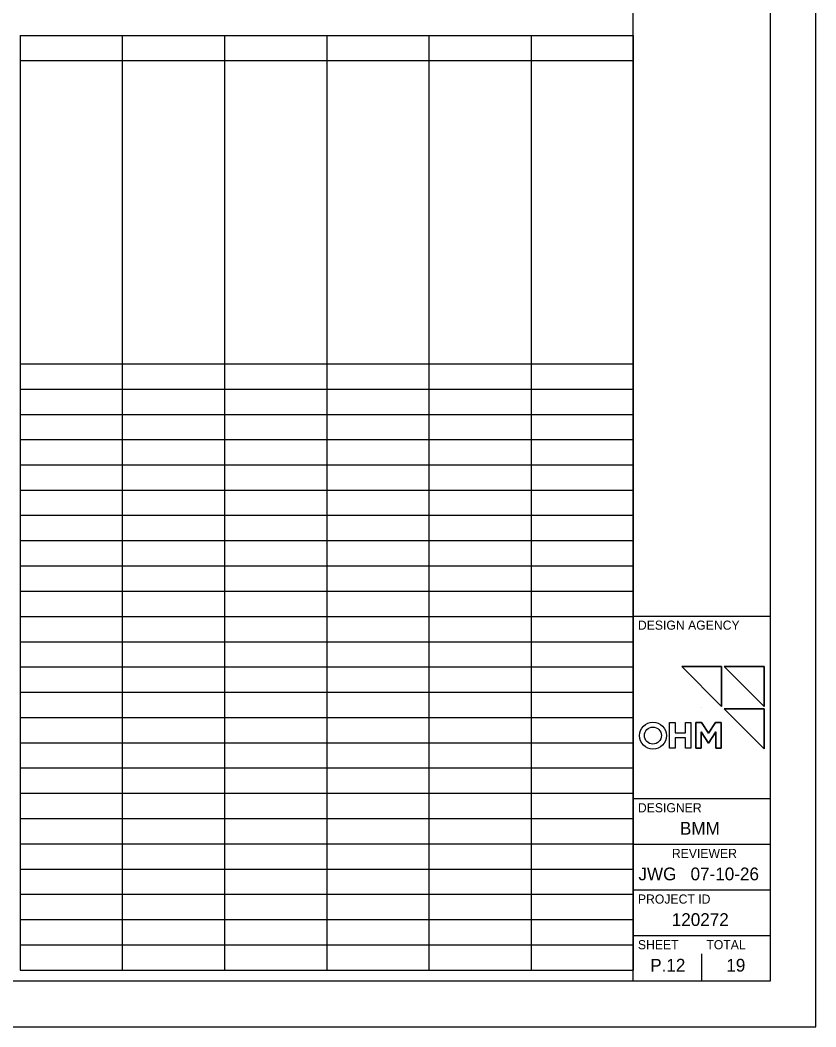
# Model space of a CAD drawing. Extents: x 0 to 34, y 0 to 22.
# Drawn here: x 25.28 to 34, y 0 to 11.03 of the extents above; entities that cross this region are included whole.
import ezdxf

# ---------------------------------------------------------------- set-up
doc = ezdxf.new("R2010")
doc.units = 0
for name, color, linetype in [('Default', 7, 'Continuous'), ('SH_Border', 7, 'Continuous'), ('SH_Cut_Line', 7, 'Continuous'), ('SH_Data', 7, 'Continuous'), ('TX_P_Misc', 7, 'Continuous')]:
    doc.layers.add(name, color=color, linetype=linetype)

msp = doc.modelspace()

# ---------------------------------------------------------------- linework, layer by layer
at = {"layer": 'Default'}
for points in [[(32.966, 3.948), (32.966, 3.51), (32.53, 3.948)], [(33.433, 3.948), (33.433, 3.51), (32.997, 3.948)], [(33.433, 3.483), (33.433, 3.045), (32.997, 3.483)], [(32.397, 3.333), (32.457, 3.333), (32.457, 3.22), (32.571, 3.22), (32.571, 3.333), (32.631, 3.333), (32.631, 3.052), (32.571, 3.052), (32.571, 3.166), (32.457, 3.166), (32.457, 3.052), (32.397, 3.052)], [(32.9, 3.335), (32.963, 3.335), (32.963, 3.052), (32.903, 3.052), (32.903, 3.233), (32.824, 3.108), (32.745, 3.233), (32.745, 3.052), (32.685, 3.052), (32.685, 3.335), (32.748, 3.335), (32.824, 3.216)]]:
    msp.add_lwpolyline(points, close=True, dxfattribs=at)
at = {"layer": 'SH_Border'}
for p, q in [((32, 0.5), (32, 21.5)), ((32, 4.5), (33.5, 4.5)), ((32, 2.5), (33.5, 2.5)), ((32, 2), (33.5, 2)), ((32, 1.5), (33.5, 1.5)), ((32, 1), (33.5, 1))]:
    msp.add_line(p, q, dxfattribs=at)
msp.add_lwpolyline([(1.5, 21.5), (33.5, 21.5), (33.5, 0.5), (1.5, 0.5)], close=True, dxfattribs=at)
at = {"layer": 'SH_Cut_Line'}
msp.add_lwpolyline([(0, 0), (34, 0), (34, 22), (0, 22)], close=True, dxfattribs=at)
at = {"layer": 'SH_Data'}
for p, q in [((25.282, 10.86), (28.641, 10.86)), ((25.282, 10.86), (25.282, 10.583)), ((26.401, 10.86), (26.401, 10.583)), ((27.521, 10.86), (27.521, 10.583)), ((28.641, 10.86), (29.761, 10.86)), ((28.641, 10.86), (28.641, 10.583)), ((29.761, 10.86), (30.88, 10.86)), ((29.761, 10.86), (29.761, 10.583)), ((30.88, 10.86), (32, 10.86)), ((30.88, 10.86), (30.88, 10.583)), ((32, 10.86), (32, 10.583)), ((25.282, 10.583), (28.641, 10.583)), ((25.282, 10.583), (25.282, 10.307)), ((26.401, 10.583), (26.401, 10.307)), ((27.521, 10.583), (27.521, 10.307)), ((28.641, 10.583), (29.761, 10.583)), ((28.641, 10.583), (28.641, 10.307)), ((29.761, 10.583), (30.88, 10.583)), ((29.761, 10.583), (29.761, 10.307)), ((30.88, 10.583), (32, 10.583)), ((30.88, 10.583), (30.88, 10.307)), ((32, 10.583), (32, 10.307)), ((25.282, 10.307), (25.282, 10.03)), ((26.401, 10.307), (26.401, 10.03)), ((27.521, 10.307), (27.521, 10.03)), ((28.641, 10.307), (28.641, 10.03)), ((29.761, 10.307), (29.761, 10.03)), ((30.88, 10.307), (30.88, 10.03)), ((32, 10.307), (32, 10.03)), ((25.282, 10.03), (25.282, 9.753)), ((26.401, 10.03), (26.401, 9.753)), ((27.521, 10.03), (27.521, 9.753)), ((28.641, 10.03), (28.641, 9.753)), ((29.761, 10.03), (29.761, 9.753)), ((30.88, 10.03), (30.88, 9.753)), ((32, 10.03), (32, 9.753)), ((25.282, 9.753), (25.282, 9.476)), ((26.401, 9.753), (26.401, 9.476)), ((27.521, 9.753), (27.521, 9.476)), ((28.641, 9.753), (28.641, 9.476)), ((29.761, 9.753), (29.761, 9.476)), ((30.88, 9.753), (30.88, 9.476)), ((32, 9.753), (32, 9.476)), ((25.282, 9.476), (25.282, 9.2)), ((26.401, 9.476), (26.401, 9.2)), ((27.521, 9.476), (27.521, 9.2)), ((28.641, 9.476), (28.641, 9.2)), ((29.761, 9.476), (29.761, 9.2)), ((30.88, 9.476), (30.88, 9.2)), ((32, 9.476), (32, 9.2)), ((25.282, 9.2), (25.282, 8.923)), ((26.401, 9.2), (26.401, 8.923)), ((27.521, 9.2), (27.521, 8.923)), ((28.641, 9.2), (28.641, 8.923)), ((29.761, 9.2), (29.761, 8.923)), ((30.88, 9.2), (30.88, 8.923)), ((32, 9.2), (32, 8.923)), ((25.282, 8.923), (25.282, 8.646)), ((26.401, 8.923), (26.401, 8.646)), ((27.521, 8.923), (27.521, 8.646)), ((28.641, 8.923), (28.641, 8.646)), ((29.761, 8.923), (29.761, 8.646)), ((30.88, 8.923), (30.88, 8.646)), ((32, 8.923), (32, 8.646)), ((25.282, 8.646), (25.282, 8.37)), ((26.401, 8.646), (26.401, 8.37)), ((27.521, 8.646), (27.521, 8.37)), ((28.641, 8.646), (28.641, 8.37)), ((29.761, 8.646), (29.761, 8.37)), ((30.88, 8.646), (30.88, 8.37)), ((32, 8.646), (32, 8.37)), ((25.282, 8.37), (25.282, 8.093)), ((26.401, 8.37), (26.401, 8.093)), ((27.521, 8.37), (27.521, 8.093)), ((28.641, 8.37), (28.641, 8.093)), ((29.761, 8.37), (29.761, 8.093)), ((30.88, 8.37), (30.88, 8.093)), ((32, 8.37), (32, 8.093)), ((25.282, 8.093), (25.282, 7.816)), ((26.401, 8.093), (26.401, 7.816)), ((27.521, 8.093), (27.521, 7.816)), ((28.641, 8.093), (28.641, 7.816)), ((29.761, 8.093), (29.761, 7.816)), ((30.88, 8.093), (30.88, 7.816)), ((32, 8.093), (32, 7.816)), ((25.282, 7.816), (25.282, 7.54)), ((26.401, 7.816), (26.401, 7.54)), ((27.521, 7.816), (27.521, 7.54)), ((28.641, 7.816), (28.641, 7.54)), ((29.761, 7.816), (29.761, 7.54)), ((30.88, 7.816), (30.88, 7.54)), ((32, 7.816), (32, 7.54)), ((25.282, 7.54), (25.282, 7.263)), ((26.401, 7.54), (26.401, 7.263)), ((27.521, 7.54), (27.521, 7.263)), ((28.641, 7.54), (28.641, 7.263)), ((29.761, 7.54), (29.761, 7.263)), ((30.88, 7.54), (30.88, 7.263)), ((32, 7.54), (32, 7.263)), ((25.282, 7.263), (28.641, 7.263)), ((25.282, 7.263), (25.282, 6.986)), ((26.401, 7.263), (26.401, 6.986)), ((27.521, 7.263), (27.521, 6.986)), ((28.641, 7.263), (29.761, 7.263)), ((28.641, 7.263), (28.641, 6.986)), ((29.761, 7.263), (30.88, 7.263)), ((29.761, 7.263), (29.761, 6.986)), ((30.88, 7.263), (32, 7.263)), ((30.88, 7.263), (30.88, 6.986)), ((32, 7.263), (32, 6.986)), ((25.282, 6.986), (28.641, 6.986)), ((25.282, 6.986), (25.282, 6.709)), ((26.401, 6.986), (26.401, 6.709)), ((27.521, 6.986), (27.521, 6.709)), ((28.641, 6.986), (29.761, 6.986)), ((28.641, 6.986), (28.641, 6.709)), ((29.761, 6.986), (30.88, 6.986)), ((29.761, 6.986), (29.761, 6.709)), ((30.88, 6.986), (32, 6.986)), ((30.88, 6.986), (30.88, 6.709)), ((32, 6.986), (32, 6.709)), ((25.282, 6.709), (28.641, 6.709)), ((25.282, 6.709), (25.282, 6.433)), ((26.401, 6.709), (26.401, 6.433)), ((27.521, 6.709), (27.521, 6.433)), ((28.641, 6.709), (29.761, 6.709)), ((28.641, 6.709), (28.641, 6.433)), ((29.761, 6.709), (30.88, 6.709)), ((29.761, 6.709), (29.761, 6.433)), ((30.88, 6.709), (32, 6.709)), ((30.88, 6.709), (30.88, 6.433)), ((32, 6.709), (32, 6.433)), ((25.282, 6.433), (28.641, 6.433)), ((25.282, 6.433), (25.282, 5.879)), ((26.401, 6.433), (26.401, 5.879)), ((27.521, 6.433), (27.521, 5.879)), ((28.641, 6.433), (29.761, 6.433)), ((28.641, 6.433), (28.641, 5.879)), ((29.761, 6.433), (30.88, 6.433)), ((29.761, 6.433), (29.761, 5.879)), ((30.88, 6.433), (32, 6.433)), ((30.88, 6.433), (30.88, 5.879)), ((32, 6.433), (32, 5.879)), ((25.282, 6.156), (28.641, 6.156)), ((28.641, 6.156), (29.761, 6.156)), ((29.761, 6.156), (30.88, 6.156)), ((30.88, 6.156), (32, 6.156)), ((25.282, 5.879), (28.641, 5.879)), ((25.282, 5.879), (25.282, 5.603)), ((26.401, 5.879), (26.401, 5.603)), ((27.521, 5.879), (27.521, 5.603)), ((28.641, 5.879), (29.761, 5.879)), ((28.641, 5.879), (28.641, 5.603)), ((29.761, 5.879), (30.88, 5.879)), ((29.761, 5.879), (29.761, 5.603)), ((30.88, 5.879), (32, 5.879)), ((30.88, 5.879), (30.88, 5.603)), ((32, 5.879), (32, 5.603)), ((25.282, 5.603), (28.641, 5.603)), ((25.282, 5.603), (25.282, 5.326)), ((26.401, 5.603), (26.401, 5.326)), ((27.521, 5.603), (27.521, 5.326)), ((28.641, 5.603), (29.761, 5.603)), ((28.641, 5.603), (28.641, 5.326)), ((29.761, 5.603), (30.88, 5.603)), ((29.761, 5.603), (29.761, 5.326)), ((30.88, 5.603), (32, 5.603)), ((30.88, 5.603), (30.88, 5.326)), ((32, 5.603), (32, 5.326)), ((25.282, 5.326), (28.641, 5.326)), ((25.282, 5.326), (25.282, 5.049)), ((26.401, 5.326), (26.401, 5.049)), ((27.521, 5.326), (27.521, 5.049)), ((28.641, 5.326), (29.761, 5.326)), ((28.641, 5.326), (28.641, 5.049)), ((29.761, 5.326), (30.88, 5.326)), ((29.761, 5.326), (29.761, 5.049)), ((30.88, 5.326), (32, 5.326)), ((30.88, 5.326), (30.88, 5.049)), ((32, 5.326), (32, 5.049)), ((25.282, 5.049), (28.641, 5.049)), ((25.282, 5.049), (25.282, 4.496)), ((26.401, 5.049), (26.401, 4.496)), ((27.521, 5.049), (27.521, 4.496)), ((28.641, 5.049), (29.761, 5.049)), ((28.641, 5.049), (28.641, 4.496)), ((29.761, 5.049), (30.88, 5.049)), ((29.761, 5.049), (29.761, 4.496)), ((30.88, 5.049), (32, 5.049)), ((30.88, 5.049), (30.88, 4.496)), ((32, 5.049), (32, 4.496)), ((25.282, 4.772), (28.641, 4.772)), ((28.641, 4.772), (29.761, 4.772)), ((29.761, 4.772), (30.88, 4.772)), ((30.88, 4.772), (32, 4.772)), ((25.282, 4.496), (28.641, 4.496)), ((25.282, 4.496), (25.282, 4.219)), ((26.401, 4.496), (26.401, 4.219)), ((27.521, 4.496), (27.521, 4.219)), ((28.641, 4.496), (29.761, 4.496)), ((28.641, 4.496), (28.641, 4.219)), ((29.761, 4.496), (30.88, 4.496)), ((29.761, 4.496), (29.761, 4.219)), ((30.88, 4.496), (32, 4.496)), ((30.88, 4.496), (30.88, 4.219)), ((32, 4.496), (32, 4.219)), ((25.282, 4.219), (28.641, 4.219)), ((25.282, 4.219), (25.282, 3.942)), ((26.401, 4.219), (26.401, 3.942)), ((27.521, 4.219), (27.521, 3.942)), ((28.641, 4.219), (29.761, 4.219)), ((28.641, 4.219), (28.641, 3.942)), ((29.761, 4.219), (30.88, 4.219)), ((29.761, 4.219), (29.761, 3.942)), ((30.88, 4.219), (32, 4.219)), ((30.88, 4.219), (30.88, 3.942)), ((32, 4.219), (32, 3.942)), ((25.282, 3.942), (28.641, 3.942)), ((25.282, 3.942), (25.282, 3.666)), ((26.401, 3.942), (26.401, 3.666)), ((27.521, 3.942), (27.521, 3.666)), ((28.641, 3.942), (29.761, 3.942)), ((28.641, 3.942), (28.641, 3.666)), ((29.761, 3.942), (30.88, 3.942)), ((29.761, 3.942), (29.761, 3.666)), ((30.88, 3.942), (32, 3.942)), ((30.88, 3.942), (30.88, 3.666)), ((32, 3.942), (32, 3.666)), ((25.282, 3.666), (28.641, 3.666)), ((25.282, 3.666), (25.282, 3.112)), ((26.401, 3.666), (26.401, 3.112)), ((27.521, 3.666), (27.521, 3.112)), ((28.641, 3.666), (29.761, 3.666)), ((28.641, 3.666), (28.641, 3.112)), ((29.761, 3.666), (30.88, 3.666)), ((29.761, 3.666), (29.761, 3.112)), ((30.88, 3.666), (32, 3.666)), ((30.88, 3.666), (30.88, 3.112)), ((32, 3.666), (32, 3.112)), ((32.75, 3.5), (32.75, 3.5)), ((25.282, 3.389), (28.641, 3.389)), ((28.641, 3.389), (29.761, 3.389)), ((29.761, 3.389), (30.88, 3.389)), ((30.88, 3.389), (32, 3.389)), ((25.282, 3.112), (28.641, 3.112)), ((25.282, 3.112), (25.282, 2.836)), ((26.401, 3.112), (26.401, 2.836)), ((27.521, 3.112), (27.521, 2.836)), ((28.641, 3.112), (29.761, 3.112)), ((28.641, 3.112), (28.641, 2.836)), ((29.761, 3.112), (30.88, 3.112)), ((29.761, 3.112), (29.761, 2.836)), ((30.88, 3.112), (32, 3.112)), ((30.88, 3.112), (30.88, 2.836)), ((32, 3.112), (32, 2.836)), ((25.282, 2.836), (28.641, 2.836)), ((25.282, 2.836), (25.282, 2.005)), ((26.401, 2.836), (26.401, 2.005)), ((27.521, 2.836), (27.521, 2.005)), ((28.641, 2.836), (29.761, 2.836)), ((28.641, 2.836), (28.641, 2.005)), ((29.761, 2.836), (30.88, 2.836)), ((29.761, 2.836), (29.761, 2.005)), ((30.88, 2.836), (32, 2.836)), ((30.88, 2.836), (30.88, 2.005)), ((32, 2.836), (32, 2.005)), ((25.282, 2.559), (28.641, 2.559)), ((28.641, 2.559), (29.761, 2.559)), ((29.761, 2.559), (30.88, 2.559)), ((30.88, 2.559), (32, 2.559)), ((25.282, 2.282), (28.641, 2.282)), ((28.641, 2.282), (29.761, 2.282)), ((29.761, 2.282), (30.88, 2.282)), ((30.88, 2.282), (32, 2.282)), ((25.282, 2.005), (28.641, 2.005)), ((25.282, 2.005), (25.282, 1.729)), ((26.401, 2.005), (26.401, 1.729)), ((27.521, 2.005), (27.521, 1.729)), ((28.641, 2.005), (29.761, 2.005)), ((28.641, 2.005), (28.641, 1.729)), ((29.761, 2.005), (30.88, 2.005)), ((29.761, 2.005), (29.761, 1.729)), ((30.88, 2.005), (32, 2.005)), ((30.88, 2.005), (30.88, 1.729)), ((32, 2.005), (32, 1.729)), ((25.282, 1.729), (28.641, 1.729)), ((25.282, 1.729), (25.282, 1.452)), ((26.401, 1.729), (26.401, 1.452)), ((27.521, 1.729), (27.521, 1.452)), ((28.641, 1.729), (29.761, 1.729)), ((28.641, 1.729), (28.641, 1.452)), ((29.761, 1.729), (30.88, 1.729)), ((29.761, 1.729), (29.761, 1.452)), ((30.88, 1.729), (32, 1.729)), ((30.88, 1.729), (30.88, 1.452)), ((32, 1.729), (32, 1.452)), ((25.282, 1.452), (28.641, 1.452)), ((25.282, 1.452), (25.282, 1.175)), ((26.401, 1.452), (26.401, 1.175)), ((27.521, 1.452), (27.521, 1.175)), ((28.641, 1.452), (29.761, 1.452)), ((28.641, 1.452), (28.641, 1.175)), ((29.761, 1.452), (30.88, 1.452)), ((29.761, 1.452), (29.761, 1.175)), ((30.88, 1.452), (32, 1.452)), ((30.88, 1.452), (30.88, 1.175)), ((32, 1.452), (32, 1.175)), ((25.282, 1.175), (28.641, 1.175)), ((25.282, 1.175), (25.282, 0.899)), ((26.401, 1.175), (26.401, 0.899)), ((27.521, 1.175), (27.521, 0.899)), ((28.641, 1.175), (29.761, 1.175)), ((28.641, 1.175), (28.641, 0.899)), ((29.761, 1.175), (30.88, 1.175)), ((29.761, 1.175), (29.761, 0.899)), ((30.88, 1.175), (32, 1.175)), ((30.88, 1.175), (30.88, 0.899)), ((32, 1.175), (32, 0.899)), ((25.282, 0.899), (28.641, 0.899)), ((25.282, 0.899), (25.282, 0.622)), ((26.401, 0.899), (26.401, 0.622)), ((27.521, 0.899), (27.521, 0.622)), ((28.641, 0.899), (29.761, 0.899)), ((28.641, 0.899), (28.641, 0.622)), ((29.761, 0.899), (30.88, 0.899)), ((29.761, 0.899), (29.761, 0.622)), ((30.88, 0.899), (32, 0.899)), ((30.88, 0.899), (30.88, 0.622)), ((32, 0.899), (32, 0.622)), ((32.75, 0.5), (32.75, 0.8)), ((32.375, 0.675), (32.375, 0.675)), ((25.282, 0.622), (28.641, 0.622)), ((28.641, 0.622), (29.761, 0.622)), ((29.761, 0.622), (30.88, 0.622)), ((30.88, 0.622), (32, 0.622))]:
    msp.add_line(p, q, dxfattribs=at)
at = {"layer": 'TX_P_Misc'}
for p, q in [((32.745, 3.052), (32.745, 3.233)), ((32.745, 3.233), (32.824, 3.108)), ((32.824, 3.108), (32.903, 3.233)), ((32.903, 3.233), (32.903, 3.052))]:
    msp.add_line(p, q, dxfattribs=at)
for points in [[(32.53, 3.948), (32.966, 3.51), (32.966, 3.948), (32.53, 3.948)], [(32.997, 3.948), (33.433, 3.51), (33.433, 3.948), (32.997, 3.948)], [(32.997, 3.483), (33.433, 3.045), (33.433, 3.483), (32.997, 3.483)], [(32.824, 3.216), (32.748, 3.335), (32.685, 3.335), (32.685, 3.052), (32.745, 3.052)], [(32.903, 3.052), (32.963, 3.052), (32.963, 3.335), (32.9, 3.335), (32.824, 3.216)]]:
    msp.add_lwpolyline(points, dxfattribs=at)
msp.add_lwpolyline([(32.397, 3.333), (32.457, 3.333), (32.457, 3.22), (32.571, 3.22), (32.571, 3.333), (32.631, 3.333), (32.631, 3.052), (32.571, 3.052), (32.571, 3.166), (32.457, 3.166), (32.457, 3.052), (32.397, 3.052)], close=True, dxfattribs=at)
for radius in [0.148, 0.148, 0.0927, 0.0927]:
    msp.add_circle((32.215, 3.19), radius, dxfattribs=at)

# ---------------------------------------------------------------- texts
at = {"layer": 'SH_Data'}
for s, height, p in [('DESIGN AGENCY', 0.1, (32.05, 4.35)), ('DESIGNER', 0.1, (32.05, 2.35)), ('BMM', 0.14, (32.511, 2.105)), ('REVIEWER', 0.1, (32.422, 1.85)), ('JWG', 0.14, (32.056, 1.605)), ('07-10-26', 0.14, (32.627, 1.605)), ('PROJECT ID', 0.1, (32.05, 1.35)), ('120272', 0.14, (32.421, 1.105)), ('SHEET', 0.1, (32.05, 0.85)), ('TOTAL', 0.1, (32.8, 0.85)), ('P.12', 0.14, (32.185, 0.605)), ('19', 0.14, (33.019, 0.605))]:
    msp.add_text(s, height=height, dxfattribs=at).set_placement(p)

doc.saveas('drawing.dxf')
